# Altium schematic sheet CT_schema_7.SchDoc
size 278 x 170 mm
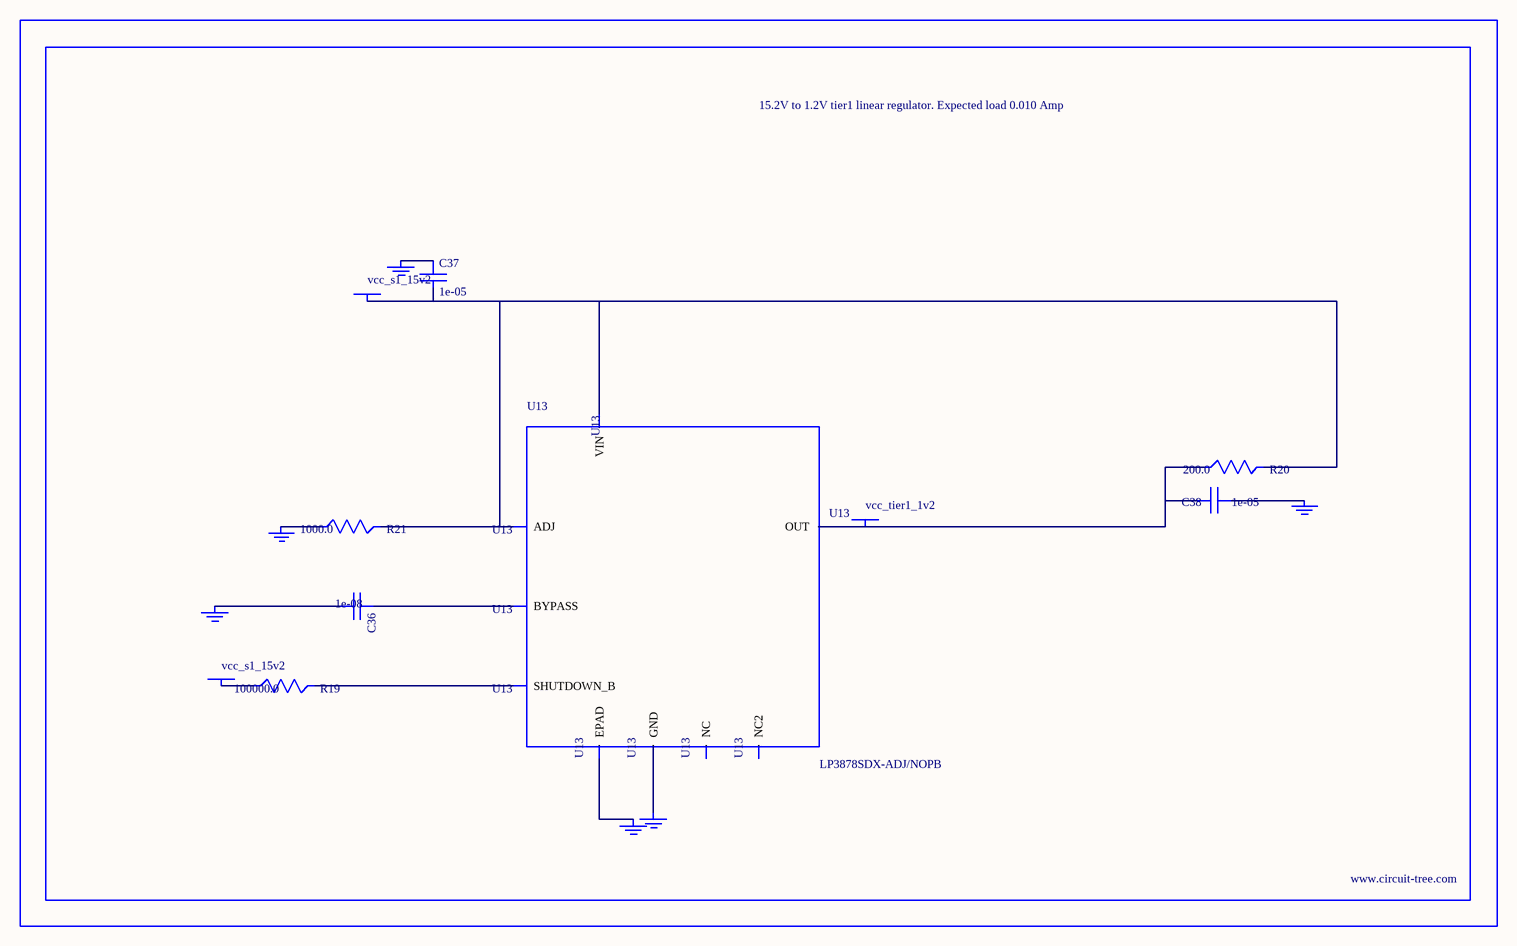
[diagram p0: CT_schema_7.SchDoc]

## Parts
BORDER6  (no value)
C36  1e-08  [C0402]
C37  1e-05  [C1210]
C38  1e-05  [C0805]
GND_INSTANCE_6_0  (no value)
GND_INSTANCE_6_1  (no value)
GND_INSTANCE_6_2  (no value)
GND_INSTANCE_6_3  (no value)
GND_INSTANCE_6_4  (no value)
GND_INSTANCE_6_5  (no value)
POWER_INSTANCE_6_0  vcc_s1_15v2
POWER_INSTANCE_6_1  vcc_s1_15v2
POWER_INSTANCE_6_2  vcc_tier1_1v2
R19  100000.0  [R0603]
R20  200.0  [R0603]
R21  1000.0  [R0603]
U13  LP3878SDX-ADJ/NOPB  [WSON-8]

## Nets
NetC36_1: C36.1 U13.1(BYPASS)
NetC36_2: C36.2 GND_INSTANCE_6_0.0(GND)
NetC37_1: C37.1 GND_INSTANCE_6_1.0(GND)
NetC37_2: C37.2 POWER_INSTANCE_6_0.0(PWR) R20.2 R21.2 U13.4(VIN) U13.6(ADJ)
NetC38_1: C38.1 GND_INSTANCE_6_2.0(GND)
NetC38_2: C38.2 POWER_INSTANCE_6_2.0(PWR) R20.1 U13.5(OUT)
NetGND_INSTANCE_6_3_0: GND_INSTANCE_6_3.0(GND) R21.1
NetGND_INSTANCE_6_4_0: GND_INSTANCE_6_4.0(GND) U13.PAD(EPAD)
NetGND_INSTANCE_6_5_0: GND_INSTANCE_6_5.0(GND) U13.3(GND)
NetPOWER_INSTANCE_6_1_0: POWER_INSTANCE_6_1.0(PWR) R19.1
NetR19_2: R19.2 U13.8(SHUTDOWN_B)

Not connected (* = marked no-connect by the designer): U13 2(NC) 7(NC2)

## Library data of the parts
BORDER6 = BORDER_PAGE6
C36 = C0402C103K3RAC
C37 = C1210C106K5PACTU
C38 = GRM219R60J106ME19D
GND_INSTANCE_6_0-GND_INSTANCE_6_5 = GND
POWER_INSTANCE_6_0-POWER_INSTANCE_6_2 = PWR
R19 = RC0603JR-07100KL
R20 = RC0603JR-07200RL
R21 = RC0603JR-071KL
